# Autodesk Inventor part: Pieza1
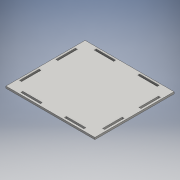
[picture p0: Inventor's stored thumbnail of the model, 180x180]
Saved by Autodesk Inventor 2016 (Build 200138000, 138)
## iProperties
Created: 2016-06
Part Number: Pieza1
Material: Genérico
Document SubType Name: Modeling
Designer: adm
Density: 1 g/cm^3
Appearance: Valor por defecto
Author: adm
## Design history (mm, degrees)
sketch "Boceto1"
  geometry: L1 (68.5, -61)-(-68.5, -61); L2 (-68.5, -61)-(-68.5, 61); L3 (-68.5, 61)-(68.5, 61); L4 (68.5, 61)-(68.5, -61); L5 (48.5, 58)-(48.5, 55); L6 (48.5, -55)-(48.5, -58); L7 (18.5, 58)-(18.5, 55); L8 (18.5, -55)-(18.5, -58); L9 (-18.5, 58)-(-18.5, 55); L10 (-18.5, -55)-(-18.5, -58); L11 (-48.5, 58)-(-48.5, 55); L12 (-48.5, -55)-(-48.5, -58); L13 (-65.5, 43)-(-62.5, 43); L14 (62.5, 43)-(65.5, 43); L15 (-65.5, 13)-(-62.5, 13); L16 (62.5, 13)-(65.5, 13); L17 (-65.5, -13)-(-62.5, -13); L18 (62.5, -13)-(65.5, -13); L19 (-65.5, -43)-(-62.5, -43); L20 (62.5, -43)-(65.5, -43); L21 (48.5, 58)-(18.5, 58); L22 (-18.5, 58)-(-48.5, 58); L23 (-48.5, 55)-(-18.5, 55); L24 (18.5, 55)-(48.5, 55); L25 (-62.5, -43)-(-62.5, -13); L26 (-62.5, 13)-(-62.5, 43); L27 (-65.5, 43)-(-65.5, 13); L28 (-65.5, -13)-(-65.5, -43); L29 (48.5, -55)-(18.5, -55); L30 (-18.5, -55)-(-48.5, -55); L31 (-48.5, -58)-(-18.5, -58); L32 (18.5, -58)-(48.5, -58); L33 (65.5, -43)-(65.5, -13); L34 (65.5, 13)-(65.5, 43); L35 (62.5, 43)-(62.5, 13); L36 (62.5, -13)-(62.5, -43); 1 further point
  constraints: 72 end point, 18 parallel, 11 horizontal, 11 perpendicular, 6 vertical
  dimensions: "d4" = 137 distance of L2.end L3.end; "d5" = 122 distance of L1.end L2.end; "d15" = 37 distance between parallel lines of L7 L9
extrude "Extrusión1" new body sketch "Boceto1" distance "d16" = 3; taper "d17" = 0 deg
node "Sólido1"
other parameters: "d3" = 3, "d12" = 18, "d14" = 18
